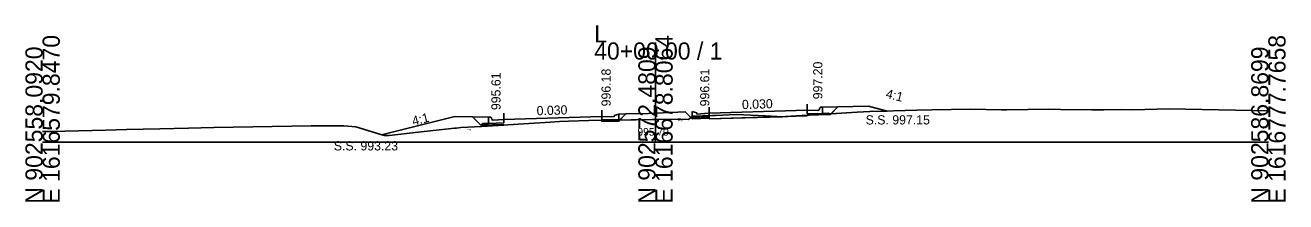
# Model space of a CAD drawing. Extents: x 1009 to 7438, y -1586 to 7964.
# Drawn here: x 3032.1 to 3237.7, y 7914 to 7942.8 of the extents above; entities that cross this region are included whole.
import ezdxf

# ---------------------------------------------------------------- set-up
doc = ezdxf.new("R2010")
doc.units = 0
for name, color, linetype in [('Exist Cross Section Cell', 7, 'Continuous'), ('Exist XS Center Line Elevation Label', 7, 'Continuous'), ('Exist XS Ground Line', 7, 'Continuous'), ('Prop XS Dump Level', 7, 'Continuous'), ('Prop XS Earthwork Shape', 7, 'Continuous'), ('Prop XS EOT Tick Mark', 7, 'Continuous'), ('Prop XS Finish Grade', 7, 'Continuous'), ('Prop XS Finish Grade CurbGutter', 7, 'Continuous'), ('Prop XS Finish Grade Earthwork', 7, 'Continuous'), ('Prop XS Finish Grade Pavement', 7, 'Continuous'), ('Prop XS Hydro Elevations', 7, 'Continuous'), ('Prop XS Pvmt Edge Slope', 7, 'Continuous'), ('Prop XS SE Text', 7, 'Continuous'), ('Prop XS Side Slope Text', 7, 'Continuous'), ('Prop XS SS Elevation Text', 7, 'Continuous'), ('Prop XS Subgrade CurbGutter', 7, 'Continuous'), ('Prop XS Subgrade Earthwork', 7, 'Continuous')]:
    doc.layers.add(name, color=color, linetype=linetype)

msp = doc.modelspace()

# ---------------------------------------------------------------- linework, layer by layer
at = {"layer": 'Exist Cross Section Cell'}
for p, q in [((3134.89, 7923.73), (3134.89, 7940)), ((3034.89, 7923.73), (3134.89, 7923.73)), ((3134.89, 7923.73), (3234.89, 7923.73))]:
    msp.add_line(p, q, dxfattribs=at)
at = {"layer": 'Exist XS Ground Line'}
for p, q in [((3177.52, 7928.97), (3179.97, 7929.03)), ((3179.97, 7929.03), (3186.34, 7929.12)), ((3186.34, 7929.12), (3191.37, 7929.04)), ((3191.37, 7929.04), (3192.22, 7929.03)), ((3192.22, 7929.03), (3199.05, 7929.1)), ((3199.05, 7929.1), (3200.96, 7929.05)), ((3200.96, 7929.05), (3206.07, 7929.01)), ((3206.07, 7929.01), (3208.02, 7929.04)), ((3208.02, 7929.04), (3210.93, 7929.09)), ((3210.93, 7929.09), (3212.7, 7929.04)), ((3212.7, 7929.04), (3218.73, 7929.15)), ((3218.73, 7929.15), (3234.89, 7928.87)), ((3114.2, 7926.78), (3117.74, 7927.02)), ((3117.74, 7927.02), (3119.23, 7927.13)), ((3119.23, 7927.13), (3120.69, 7927.17)), ((3120.69, 7927.17), (3124, 7927.26)), ((3124, 7927.26), (3134.41, 7927.42)), ((3134.41, 7927.42), (3134.89, 7927.43)), ((3134.89, 7927.43), (3138.53, 7927.49)), ((3138.53, 7927.49), (3139.04, 7927.48)), ((3139.04, 7927.48), (3140.25, 7927.46)), ((3140.25, 7927.46), (3140.91, 7927.98)), ((3140.91, 7927.98), (3145.84, 7928.13)), ((3145.84, 7928.13), (3148.03, 7928.24)), ((3148.03, 7928.24), (3152.84, 7928.01)), ((3152.84, 7928.01), (3155.63, 7927.9)), ((3155.63, 7927.9), (3167.77, 7928.61)), ((3167.77, 7928.61), (3169.86, 7928.74)), ((3169.86, 7928.74), (3177.52, 7928.97)), ((3034.89, 7925.46), (3036.36, 7925.49)), ((3036.36, 7925.49), (3038.49, 7925.54)), ((3038.49, 7925.54), (3045.18, 7925.69)), ((3045.18, 7925.69), (3048.6, 7925.79)), ((3048.6, 7925.79), (3054, 7925.92)), ((3054, 7925.92), (3058.7, 7926.05)), ((3058.7, 7926.05), (3062.82, 7926.16)), ((3062.82, 7926.16), (3078.73, 7926.41)), ((3078.73, 7926.41), (3079.17, 7926.42)), ((3079.17, 7926.42), (3084.05, 7926.39)), ((3084.05, 7926.39), (3086.02, 7926.22)), ((3086.02, 7926.22), (3090.06, 7925)), ((3090.06, 7925), (3090.68, 7924.81)), ((3091.43, 7924.81), (3096.16, 7925.37)), ((3096.16, 7925.37), (3102.07, 7926.02)), ((3102.07, 7926.02), (3102.41, 7926.05)), ((3102.41, 7926.05), (3103.13, 7926.12)), ((3103.13, 7926.12), (3106.52, 7926.32)), ((3106.52, 7926.32), (3114.2, 7926.78)), ((3090.68, 7924.81), (3091.43, 7924.81))]:
    msp.add_line(p, q, dxfattribs=at)
at = {"layer": 'Prop XS Dump Level'}
for p, q in [((3110.14, 7927.46), (3126.14, 7927.94)), ((3110.14, 7927.46), (3126.14, 7927.94)), ((3143.64, 7928.47), (3159.64, 7928.95)), ((3143.64, 7928.47), (3159.64, 7928.95))]:
    msp.add_line(p, q, dxfattribs=at)
at = {"layer": 'Prop XS Earthwork Shape'}
for points in [[(3169.86, 7928.74), (3172.69, 7928.82), (3169.64, 7929.59), (3164.64, 7929.48), (3163.53, 7928.36), (3167.77, 7928.61)], [(3102.14, 7927.94), (3090.21, 7924.95), (3090.68, 7924.81), (3091.43, 7924.81), (3096.16, 7925.37), (3102.07, 7926.02), (3102.41, 7926.05), (3103.13, 7926.12), (3106.52, 7926.32), (3110.14, 7926.54), (3110.14, 7926.63), (3106.39, 7926.52), (3105.04, 7927.88)], [(3128.75, 7927.33), (3128.89, 7927.19), (3126.14, 7927.11), (3126.14, 7927.29)], [(3128.75, 7927.33), (3128.89, 7927.19), (3129.03, 7927.34)], [(3138.53, 7927.49), (3139.04, 7927.48), (3140.25, 7927.46), (3140.66, 7927.78), (3139.74, 7928.7), (3133.76, 7928.42), (3130.12, 7928.35), (3130.04, 7928.35), (3129.03, 7927.34), (3134.41, 7927.42), (3134.89, 7927.43)], [(3141.14, 7927.81), (3140.88, 7927.55), (3140.66, 7927.78), (3140.9, 7927.97), (3140.9, 7927.81)], [(3141.14, 7927.81), (3140.88, 7927.55), (3143.64, 7927.64), (3143.64, 7927.89), (3142.14, 7927.84)], [(3143.64, 7927.89), (3142.14, 7927.84), (3141.14, 7927.81), (3140.9, 7927.81), (3140.9, 7927.97), (3140.91, 7927.98), (3143.64, 7928.06)], [(3143.64, 7927.55), (3143.64, 7927.64), (3143.64, 7927.89), (3143.64, 7928.06), (3145.84, 7928.13), (3148.03, 7928.24), (3152.84, 7928.01), (3155.43, 7927.9)], [(3155.63, 7927.9), (3156.11, 7927.92), (3155.43, 7927.9)], [(3159.64, 7928.03), (3159.64, 7928.12), (3163.39, 7928.23), (3163.27, 7928.35), (3156.11, 7927.92)], [(3163.39, 7928.23), (3163.53, 7928.36), (3163.27, 7928.35)]]:
    msp.add_lwpolyline(points, close=True, dxfattribs=at)
at = {"layer": 'Prop XS EOT Tick Mark'}
for p, q in [((3143.64, 7928.47), (3143.64, 7929.47)), ((3159.64, 7928.95), (3159.64, 7929.95)), ((3110.14, 7927.46), (3110.14, 7928.46)), ((3126.14, 7927.94), (3126.14, 7928.94))]:
    msp.add_line(p, q, dxfattribs=at)
at = {"layer": 'Prop XS Finish Grade'}
for p, q in [((3162.14, 7929.43), (3164.64, 7929.48)), ((3107.64, 7927.82), (3105.04, 7927.88)), ((3128.89, 7928.32), (3130.12, 7928.35))]:
    msp.add_line(p, q, dxfattribs=at)
at = {"layer": 'Prop XS Finish Grade CurbGutter'}
for p, q in [((3161.52, 7928.95), (3161.61, 7929.05)), ((3161.61, 7929.05), (3161.68, 7929.3)), ((3161.68, 7929.3), (3161.77, 7929.39)), ((3161.89, 7929.43), (3161.77, 7929.39)), ((3162.14, 7929.43), (3161.89, 7929.43)), ((3107.64, 7927.82), (3107.89, 7927.82)), ((3107.89, 7927.82), (3108.02, 7927.8)), ((3108.11, 7927.71), (3108.02, 7927.8)), ((3108.18, 7927.46), (3108.11, 7927.71)), ((3108.27, 7927.36), (3108.18, 7927.46)), ((3108.39, 7927.34), (3108.27, 7927.36)), ((3110.14, 7927.46), (3108.39, 7927.34)), ((3126.14, 7927.94), (3128.14, 7927.9)), ((3128.14, 7928.07), (3128.89, 7928.32)), ((3128.14, 7927.9), (3128.14, 7928.07)), ((3141.65, 7928.5), (3140.9, 7928.75)), ((3141.65, 7928.33), (3141.65, 7928.5)), ((3143.64, 7928.47), (3141.65, 7928.33)), ((3143.64, 7928.47), (3142.89, 7928.42)), ((3159.64, 7928.95), (3161.39, 7928.93)), ((3161.39, 7928.93), (3161.52, 7928.95))]:
    msp.add_line(p, q, dxfattribs=at)
at = {"layer": 'Prop XS Finish Grade Earthwork'}
for p, q in [((3164.64, 7929.48), (3169.64, 7929.59)), ((3169.64, 7929.59), (3172.69, 7928.82)), ((3102.14, 7927.94), (3090.21, 7924.95)), ((3105.04, 7927.88), (3102.14, 7927.94)), ((3130.12, 7928.35), (3133.76, 7928.42)), ((3139.74, 7928.7), (3133.76, 7928.42))]:
    msp.add_line(p, q, dxfattribs=at)
at = {"layer": 'Prop XS Finish Grade Pavement'}
for p, q in [((3110.14, 7927.46), (3126.14, 7927.94)), ((3143.64, 7928.47), (3159.64, 7928.95))]:
    msp.add_line(p, q, dxfattribs=at)
at = {"layer": 'Prop XS Pvmt Edge Slope'}
for p, q in [((3127.64, 7927.39), (3128.89, 7927.42)), ((3127.64, 7927.39), (3128.67, 7927.41)), ((3128.67, 7927.41), (3128.89, 7927.19)), ((3141.14, 7927.81), (3140.88, 7927.55)), ((3142.14, 7927.84), (3140.9, 7927.81)), ((3162.14, 7928.44), (3163.14, 7928.47)), ((3163.14, 7928.47), (3163.39, 7928.23)), ((3106.64, 7926.78), (3106.39, 7926.52)), ((3107.64, 7926.81), (3106.64, 7926.78))]:
    msp.add_line(p, q, dxfattribs=at)
at = {"layer": 'Prop XS Subgrade CurbGutter'}
for p, q in [((3162.14, 7928.44), (3162.14, 7929.43)), ((3107.64, 7926.81), (3107.64, 7927.82)), ((3110.14, 7927.46), (3110.14, 7926.88)), ((3126.14, 7927.94), (3126.14, 7927.36)), ((3126.14, 7927.36), (3127.64, 7927.39)), ((3128.89, 7927.42), (3128.89, 7928.32)), ((3140.9, 7927.81), (3140.9, 7928.75)), ((3143.64, 7927.89), (3142.14, 7927.84)), ((3143.64, 7928.47), (3143.64, 7927.89)), ((3159.64, 7928.95), (3159.64, 7928.37)), ((3159.64, 7928.37), (3162.14, 7928.44)), ((3110.14, 7926.88), (3107.64, 7926.81))]:
    msp.add_line(p, q, dxfattribs=at)
at = {"layer": 'Prop XS Subgrade Earthwork'}
for p, q in [((3163.39, 7928.23), (3164.64, 7929.48)), ((3106.39, 7926.52), (3105.04, 7927.88)), ((3126.14, 7927.11), (3126.14, 7927.29)), ((3126.14, 7927.11), (3128.89, 7927.19)), ((3128.89, 7927.19), (3130.04, 7928.35)), ((3140.88, 7927.55), (3139.74, 7928.7)), ((3143.64, 7927.64), (3140.88, 7927.55)), ((3143.64, 7927.55), (3143.64, 7928.06)), ((3143.64, 7927.55), (3159.64, 7928.03)), ((3143.64, 7927.55), (3143.64, 7927.64)), ((3159.64, 7928.12), (3163.39, 7928.23)), ((3159.64, 7928.03), (3159.64, 7928.12)), ((3110.14, 7926.63), (3106.39, 7926.52)), ((3110.14, 7926.54), (3110.14, 7926.63))]:
    msp.add_line(p, q, dxfattribs=at)

# ---------------------------------------------------------------- texts
at = {"layer": 'Exist Cross Section Cell'}
for s, p in [('L', (3124.89, 7940)), ('40+00.00 / 1', (3124.89, 7937.2))]:
    msp.add_text(s, height=2.8, dxfattribs=at).set_placement(p)
for s, p in [('E 1616579.8470', (3037.69, 7913.73)), ('E 1616678.8064', (3137.69, 7913.73)), ('E 1616777.7658', (3237.69, 7913.73)), ('N 902558.0920', (3034.89, 7913.73)), ('N 902572.4809', (3134.89, 7913.73)), ('N 902586.8699', (3234.89, 7913.73))]:
    msp.add_text(s, height=2.8, rotation=90, dxfattribs=at).set_placement(p)
at = {"layer": 'Exist XS Center Line Elevation Label'}
msp.add_text('995.70', height=1.25, dxfattribs=at).set_placement((3131.94, 7924.8))
at = {"layer": 'Prop XS Dump Level'}
for p in [(3138.54, 7927.18), (3138.54, 7927.18), (3138.54, 7927.18), (3104.08, 7925.66)]:
    msp.add_text('Eop', height=0.3, dxfattribs=at).set_placement(p)
at = {"layer": 'Prop XS Hydro Elevations'}
for s, p in [('996.18', (3127.58, 7929.58)), ('996.61', (3143.68, 7929.58)), ('997.20', (3162.12, 7930.73)), ('995.61', (3109.61, 7928.97))]:
    msp.add_text(s, height=1.5, rotation=90, dxfattribs=at).set_placement(p)
at = {"layer": 'Prop XS SE Text'}
for p in [(3115.52, 7928.12), (3149.02, 7929.13)]:
    msp.add_text('0.030', height=1.5, rotation=1.7184, dxfattribs=at).set_placement(p)
at = {"layer": 'Prop XS Side Slope Text'}
for rotation, p in [(345.9638, (3172.37, 7930.99)), (14.0362, (3095.37, 7926.42))]:
    msp.add_text('4:1', height=1.5, rotation=rotation, dxfattribs=at).set_placement(p)
at = {"layer": 'Prop XS SS Elevation Text'}
for s, p in [('S.S. 997.15', (3169.18, 7926.63)), ('S.S. 993.23', (3082.4, 7922.4))]:
    msp.add_text(s, height=1.5, dxfattribs=at).set_placement(p)

doc.saveas('drawing.dxf')
